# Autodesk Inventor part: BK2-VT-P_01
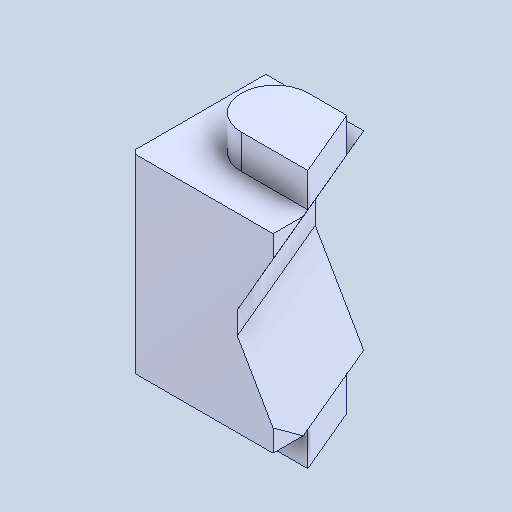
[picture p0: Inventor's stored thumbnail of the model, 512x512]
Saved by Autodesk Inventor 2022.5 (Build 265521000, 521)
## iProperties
Created: 2024-08
Part Number: BK2-VT-P_01
Material: 一般
Document SubType Name: Modeling
Designer: ImaoCorp
Density: 1 g/cm^3
Appearance: 既定
Author: ImaoCorp
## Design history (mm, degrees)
feature "BK2-VT-P_01"
node "ソリッド1"
